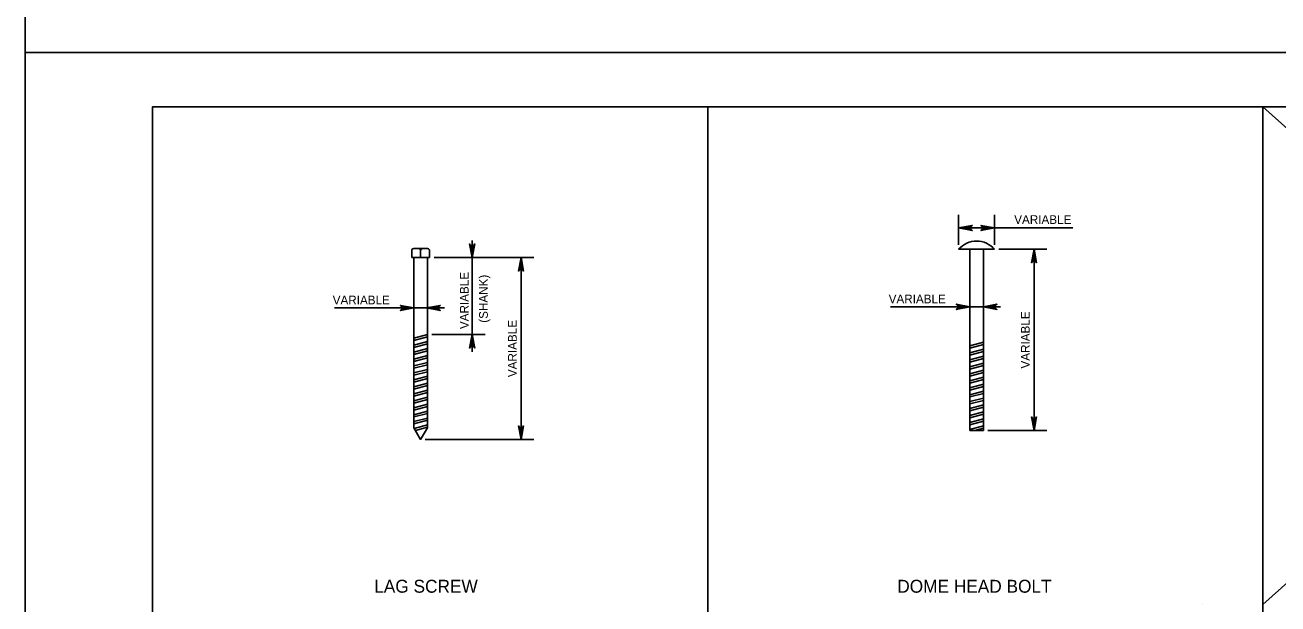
# Model space of a CAD drawing. Extents: x 179 to 454, y -271 to 54.
# Drawn here: x 360.76 to 377.97, y -29.58 to -21.62 of the extents above; entities that cross this region are included whole.
import ezdxf

# ---------------------------------------------------------------- set-up
doc = ezdxf.new("R2010")
doc.units = 0
for name, color, linetype in [('Level 1', 7, 'Continuous'), ('Level 3', 7, 'Continuous'), ('Level 4', 7, 'Continuous'), ('Level 41', 7, 'Continuous'), ('Level 5', 7, 'Continuous'), ('Level 62', 7, 'Continuous'), ('Level 63', 7, 'Continuous')]:
    doc.layers.add(name, color=color, linetype=linetype)

msp = doc.modelspace()

# ---------------------------------------------------------------- linework, layer by layer
at = {"layer": 'Level 1'}
msp.add_lwpolyline([(362.513, -43.25), (394.013, -43.25), (394.013, -22.75), (362.513, -22.75)], close=True, dxfattribs=at)
at = {"layer": 'Level 3'}
for p, q in [((370.138, -43.25), (370.138, -22.75)), ((377.763, -43.25), (377.763, -22.75)), ((373.584, -24.643), (373.584, -24.234)), ((374.077, -24.643), (374.077, -24.234)), ((373.584, -24.412), (375.151, -24.412)), ((374.077, -24.412), (374.077, -24.412)), ((374.138, -24.705), (374.796, -24.705)), ((374.619, -27.193), (374.619, -24.705)), ((366.38, -24.819), (367.752, -24.819)), ((367.575, -27.316), (367.575, -24.819)), ((367.575, -24.819), (367.575, -24.819)), ((367.575, -24.937), (367.575, -25.055)), ((366.103, -25.576), (366.103, -25.333)), ((366.288, -25.568), (366.288, -25.333)), ((373.738, -25.451), (373.738, -25.672)), ((373.923, -25.451), (373.923, -25.672)), ((365.985, -25.51), (365.015, -25.51)), ((366.288, -25.51), (366.103, -25.51)), ((366.406, -25.51), (366.524, -25.51)), ((373.62, -25.495), (372.65, -25.495)), ((373.923, -25.495), (373.738, -25.495)), ((374.041, -25.495), (374.159, -25.495)), ((366.257, -27.316), (367.752, -27.316)), ((373.984, -27.193), (374.796, -27.193)), ((376.935, -29.569), (376.935, -29.569))]:
    msp.add_line(p, q, dxfattribs=at)
for points in [[(373.584, -24.412), (373.771, -24.377), (373.756, -24.387), (373.749, -24.399), (373.747, -24.412), (373.749, -24.424), (373.756, -24.437), (373.771, -24.447), (373.584, -24.412), (373.756, -24.437), (373.749, -24.424), (373.584, -24.412), (373.747, -24.412), (373.749, -24.399), (373.584, -24.412), (373.756, -24.387)], [(374.077, -24.412), (373.89, -24.447), (373.904, -24.437), (373.912, -24.424), (373.914, -24.412), (373.912, -24.399), (373.904, -24.387), (373.89, -24.377), (374.077, -24.412), (373.904, -24.387), (373.912, -24.399), (374.077, -24.412), (373.914, -24.412), (373.912, -24.424), (374.077, -24.412), (373.904, -24.437)], [(366.903, -24.819), (366.868, -24.632), (366.878, -24.647), (366.891, -24.654), (366.903, -24.656), (366.916, -24.654), (366.928, -24.647), (366.938, -24.632), (366.903, -24.819), (366.928, -24.647), (366.916, -24.654), (366.903, -24.819), (366.903, -24.656), (366.891, -24.654), (366.903, -24.819), (366.878, -24.647)], [(374.619, -24.705), (374.654, -24.891), (374.644, -24.877), (374.631, -24.869), (374.619, -24.867), (374.606, -24.869), (374.594, -24.877), (374.584, -24.891), (374.619, -24.705), (374.594, -24.877), (374.606, -24.869), (374.619, -24.705), (374.619, -24.867), (374.631, -24.869), (374.619, -24.705), (374.644, -24.877)], [(367.575, -24.819), (367.61, -25.005), (367.6, -24.991), (367.587, -24.983), (367.575, -24.981), (367.562, -24.983), (367.55, -24.991), (367.54, -25.005), (367.575, -24.819), (367.55, -24.991), (367.562, -24.983), (367.575, -24.819), (367.575, -24.981), (367.587, -24.983), (367.575, -24.819), (367.6, -24.991)], [(373.738, -25.495), (373.552, -25.53), (373.566, -25.52), (373.574, -25.508), (373.576, -25.495), (373.574, -25.483), (373.566, -25.47), (373.552, -25.46), (373.738, -25.495), (373.566, -25.47), (373.574, -25.483), (373.738, -25.495), (373.576, -25.495), (373.574, -25.508), (373.738, -25.495), (373.566, -25.52)], [(373.923, -25.495), (374.109, -25.46), (374.095, -25.47), (374.087, -25.483), (374.085, -25.495), (374.087, -25.508), (374.095, -25.52), (374.109, -25.53), (373.923, -25.495), (374.095, -25.52), (374.087, -25.508), (373.923, -25.495), (374.085, -25.495), (374.087, -25.483), (373.923, -25.495), (374.095, -25.47)], [(366.103, -25.51), (365.917, -25.545), (365.931, -25.535), (365.939, -25.523), (365.941, -25.51), (365.939, -25.498), (365.931, -25.485), (365.917, -25.475), (366.103, -25.51), (365.931, -25.485), (365.939, -25.498), (366.103, -25.51), (365.941, -25.51), (365.939, -25.523), (366.103, -25.51), (365.931, -25.535)], [(366.278, -25.51), (366.464, -25.475), (366.45, -25.485), (366.442, -25.498), (366.44, -25.51), (366.442, -25.523), (366.45, -25.535), (366.464, -25.545), (366.278, -25.51), (366.45, -25.535), (366.442, -25.523), (366.278, -25.51), (366.44, -25.51), (366.442, -25.498), (366.278, -25.51), (366.45, -25.485)], [(366.903, -25.876), (366.938, -26.063), (366.928, -26.048), (366.916, -26.041), (366.903, -26.039), (366.891, -26.041), (366.878, -26.048), (366.868, -26.063), (366.903, -25.876), (366.878, -26.048), (366.891, -26.041), (366.903, -25.876), (366.903, -26.039), (366.916, -26.041), (366.903, -25.876), (366.928, -26.048)], [(374.619, -27.193), (374.584, -27.007), (374.594, -27.021), (374.606, -27.028), (374.619, -27.03), (374.631, -27.028), (374.644, -27.021), (374.654, -27.007), (374.619, -27.193), (374.644, -27.021), (374.631, -27.028), (374.619, -27.193), (374.619, -27.03), (374.606, -27.028), (374.619, -27.193), (374.594, -27.021)], [(367.575, -27.316), (367.54, -27.13), (367.55, -27.144), (367.562, -27.152), (367.575, -27.154), (367.587, -27.152), (367.6, -27.144), (367.61, -27.13), (367.575, -27.316), (367.6, -27.144), (367.587, -27.152), (367.575, -27.316), (367.575, -27.154), (367.562, -27.152), (367.575, -27.316), (367.55, -27.144)]]:
    msp.add_lwpolyline(points, dxfattribs=at)
for points in [[(373.703, -24.431), (373.703, -24.392), (373.584, -24.412)], [(373.959, -24.431), (373.959, -24.392), (374.077, -24.412)], [(374.638, -24.823), (374.599, -24.823), (374.619, -24.705)], [(367.594, -24.937), (367.555, -24.937), (367.575, -24.819)], [(365.985, -25.491), (365.985, -25.53), (366.103, -25.51)], [(366.406, -25.491), (366.406, -25.53), (366.288, -25.51)], [(373.62, -25.476), (373.62, -25.515), (373.738, -25.495)], [(374.041, -25.476), (374.041, -25.515), (373.923, -25.495)], [(374.638, -27.075), (374.599, -27.075), (374.619, -27.193)], [(367.594, -27.198), (367.555, -27.198), (367.575, -27.316)]]:
    msp.add_lwpolyline(points, close=True, dxfattribs=at)
at = {"layer": 'Level 4'}
for p, q in [((366.903, -24.701), (366.903, -24.583)), ((366.073, -24.723), (366.073, -24.819)), ((366.073, -24.723), (366.073, -24.723)), ((366.1, -24.696), (366.168, -24.696)), ((366.168, -24.696), (366.292, -24.696)), ((366.196, -24.723), (366.196, -24.819)), ((366.319, -24.723), (366.319, -24.819)), ((366.319, -24.723), (366.319, -24.723)), ((373.584, -24.705), (373.584, -24.705)), ((373.584, -24.705), (374.077, -24.705)), ((373.738, -24.705), (373.738, -25.972)), ((373.923, -24.705), (373.923, -25.972)), ((374.077, -24.705), (374.077, -24.705)), ((366.073, -24.819), (366.103, -24.819)), ((366.103, -24.819), (366.103, -25.865)), ((366.103, -24.819), (366.288, -24.819)), ((366.288, -24.819), (366.288, -25.865)), ((366.319, -24.819), (366.288, -24.819)), ((366.319, -24.819), (366.319, -24.819)), ((366.609, -24.819), (367.08, -24.819)), ((366.903, -25.876), (366.903, -24.819)), ((366.086, -25.884), (366.086, -25.884)), ((366.103, -25.865), (366.103, -27.156)), ((366.288, -25.865), (366.288, -27.156)), ((366.349, -25.876), (367.08, -25.876)), ((373.738, -25.972), (373.738, -27.193)), ((373.923, -25.972), (373.923, -27.193)), ((366.903, -25.994), (366.903, -26.113)), ((366.196, -27.316), (366.196, -27.316)), ((373.738, -27.193), (373.923, -27.193)), ((373.923, -27.193), (373.923, -27.193))]:
    msp.add_line(p, q, dxfattribs=at)
for points in [[(366.884, -24.701), (366.923, -24.701), (366.903, -24.819)], [(366.884, -25.994), (366.923, -25.994), (366.903, -25.876)]]:
    msp.add_lwpolyline(points, close=True, dxfattribs=at)
msp.add_lwpolyline([(366.288, -27.156), (366.196, -27.316), (366.103, -27.156)], dxfattribs=at)
for centre, radius, start, end in [((373.83, -24.917), 0.325, 40.7962, 139.2038), ((366.1, -24.723), 0.0272, 90, 180), ((366.168, -24.723), 0.0272, 0, 90), ((366.223, -24.723), 0.0272, 90, 180), ((366.291, -24.723), 0.0272, 0, 90)]:
    msp.add_arc(centre, radius, start, end, dxfattribs=at)
at = {"layer": 'Level 41'}
for p, q in [((377.763, -22.75), (385.388, -29.583)), ((385.388, -22.75), (377.763, -29.583))]:
    msp.add_line(p, q, dxfattribs=at)
at = {"layer": 'Level 5'}
for p, q in [((366.103, -25.926), (366.288, -25.876)), ((366.103, -25.958), (366.288, -25.908)), ((366.103, -26.021), (366.288, -25.972)), ((366.103, -26.053), (366.288, -26.004)), ((366.103, -26.117), (366.288, -26.067)), ((366.103, -26.149), (366.288, -26.099)), ((373.738, -26.033), (373.923, -25.983)), ((373.738, -26.065), (373.923, -26.015)), ((373.738, -26.128), (373.923, -26.079)), ((373.738, -26.16), (373.923, -26.111)), ((366.103, -26.212), (366.288, -26.163)), ((366.103, -26.244), (366.288, -26.195)), ((366.103, -26.308), (366.288, -26.258)), ((366.103, -26.34), (366.288, -26.29)), ((373.738, -26.224), (373.923, -26.175)), ((373.738, -26.256), (373.923, -26.206)), ((373.738, -26.32), (373.923, -26.27)), ((373.738, -26.351), (373.923, -26.302)), ((366.103, -26.403), (366.288, -26.354)), ((366.103, -26.435), (366.288, -26.386)), ((366.103, -26.499), (366.288, -26.45)), ((366.103, -26.531), (366.288, -26.481)), ((373.738, -26.415), (373.923, -26.366)), ((373.738, -26.447), (373.923, -26.398)), ((373.738, -26.511), (373.923, -26.461)), ((373.738, -26.543), (373.923, -26.493)), ((366.103, -26.594), (366.288, -26.545)), ((366.103, -26.626), (366.288, -26.577)), ((366.103, -26.69), (366.288, -26.64)), ((373.738, -26.606), (373.923, -26.557)), ((373.738, -26.638), (373.923, -26.589)), ((373.738, -26.702), (373.923, -26.652)), ((366.103, -26.722), (366.288, -26.672)), ((366.103, -26.785), (366.288, -26.736)), ((366.103, -26.817), (366.288, -26.768)), ((366.103, -26.881), (366.288, -26.832)), ((373.738, -26.733), (373.923, -26.684)), ((373.738, -26.797), (373.923, -26.748)), ((373.738, -26.829), (373.923, -26.78)), ((366.103, -26.913), (366.288, -26.863)), ((366.103, -26.977), (366.288, -26.927)), ((366.103, -27.008), (366.288, -26.959)), ((373.738, -26.893), (373.923, -26.843)), ((373.738, -26.925), (373.923, -26.875)), ((373.738, -26.988), (373.923, -26.939)), ((373.738, -27.02), (373.923, -26.971)), ((366.103, -27.072), (366.288, -27.023)), ((366.103, -27.104), (366.288, -27.054)), ((366.109, -27.166), (366.288, -27.118)), ((366.125, -27.194), (366.288, -27.15)), ((373.738, -27.084), (373.923, -27.034)), ((373.738, -27.116), (373.923, -27.066)), ((373.738, -27.179), (373.923, -27.13)), ((373.806, -27.193), (373.923, -27.162))]:
    msp.add_line(p, q, dxfattribs=at)
at = {"layer": 'Level 62'}
msp.add_line((360.763, -22), (360.763, -22), dxfattribs=at)
at = {"layer": 'Level 63'}
for points in [[(360.763, -22), (394.763, -22), (394.763, 0), (360.763, 0)], [(360.763, -44), (394.763, -44), (394.763, -22), (360.763, -22)]]:
    msp.add_lwpolyline(points, close=True, dxfattribs=at)

# ---------------------------------------------------------------- texts
at = {"layer": 'Level 3'}
for s, height, p in [('VARIABLE', 0.12, (374.347, -24.357)), ('VARIABLE', 0.12, (364.988, -25.462)), ('VARIABLE', 0.12, (372.623, -25.447)), ('LAG SCREW', 0.1772, (365.558, -29.422)), ('DOME HEAD BOLT', 0.17717, (372.741, -29.422))]:
    msp.add_text(s, height=height, dxfattribs=at).set_placement(p)
for p in [(374.56, -26.343), (367.516, -26.461)]:
    msp.add_text('VARIABLE', height=0.12, rotation=90, dxfattribs=at).set_placement(p)
at = {"layer": 'Level 4'}
for s, p in [('VARIABLE', (366.855, -25.801)), ('(SHANK)', (367.118, -25.714))]:
    msp.add_text(s, height=0.12, rotation=90, dxfattribs=at).set_placement(p)

doc.saveas('drawing.dxf')
